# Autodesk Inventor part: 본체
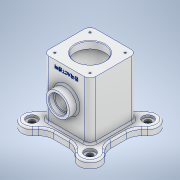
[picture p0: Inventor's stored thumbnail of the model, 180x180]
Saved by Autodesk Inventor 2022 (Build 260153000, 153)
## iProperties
Created: 2022-05
Part Number: 본체
Material: 알루미늄 6061
Document SubType Name: Modeling
Designer: Admin
Density: 2.7 g/cm^3
Appearance: 알루미늄 - 평지
Mass: 1073.02 g
Surface Area: 877.331 cm^2
Volume: 397.416 cm^3
Author: Admin
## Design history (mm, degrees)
sketch "스케치1"
  geometry: L1 (49, 49)-(-49, 49); L2 (-49, 49)-(-49, -49); L3 (-49, -49)-(49, -49); L4 (49, -49)-(49, 49); L5 (49, 49)-(-49, -49); L6 (-49, 49)-(49, -49); L7 (49, -49)-(-49, 49); L8 (61.728, -36.272)-(-36.272, 61.728); L9 (-61.728, 36.272)-(36.272, -61.728); L10 (36.272, 61.728)-(-61.728, -36.272); L11 (-36.272, -61.728)-(61.728, 36.272); L12 (104.238, 0)-(-104.238, 0) reference; L13 (0, -104.238)-(0, 104.238) reference; A1 r 18 centre (49, -49) between (36.272, -61.728) and (61.728, -36.272); A2 r 18 centre (-49, 49) between (-36.272, 61.728) and (-61.728, 36.272); A3 r 18 centre (49, 49) between (61.728, 36.272) and (36.272, 61.728); A4 r 18 centre (-49, -49) between (-61.728, -36.272) and (-36.272, -61.728); 11 further points
  constraints: 24 end point, 8 point on circle, 8 tangent, 4 centre point, 4 midpoint, 3 perpendicular, 1 collinear
  dimensions: "d0" = 98 distance of L3.end L1.start; "d1" = 98 distance of L2.end L3.end; "d2" = 36 distance between parallel lines of L10 L11; "d3" = 36 distance between parallel lines of L9 L8; "d73" = 45 deg angle of L5 L13
extrude "돌출1" new body sketch "스케치1" distance "d4" = 12; taper "d5" = 0 deg
sketch "스케치2" dims "d6" = 140
  geometry: L1 (0, 0)-(-75.016, -75.016); L2 (-104.02, 0)-(99.003, 0) reference; L3 (0, 99.003)-(0, -104.02) reference; 2 further points
  constraints: 2 end point, 1 coincident, 1 point on line, 3 other
  dimensions: "d7" = 45 deg angle of L2 L1
hole "구멍1" sketch "스케치2" at (-49.497, -49.497) diameter "d9" = 10; stored, may be unused: countersink angle "d13" = 90 deg, drill point angle "d15" = 118 deg; dims "d10" = 8, "d11" = 18, "d12" = 4, "d14" = 11.8
sketch "스케치3"
  geometry: L1 (-40, -40)-(40, -40); L2 (40, -40)-(40, 40); L3 (40, 40)-(-40, 40); L4 (-40, 40)-(-40, -40); L5 (-40, -40)-(40, 40); L6 (40, -40)-(-40, 40); 1 further point
  constraints: 12 end point, 2 midpoint, 2 parallel, 1 horizontal, 1 perpendicular
  dimensions: "d16" = 80 distance of L2.end L3.end; "d17" = 80 distance of L3.end L1.start
extrude "돌출2" join sketch "스케치3" distance "d18" = 98; taper "d19" = 0 deg
node "작업 평면1"
sketch "스케치4"
  geometry: L1 (67, 12)-(36.272, 12) reference; C1 r 20 at (0, 61); 2 further points
  constraints: 1 centre point, 1 vertical alignment
  dimensions: "d21" = 40 diameter of C1; "d22" = 49 distance from line of L1 C1.centre
extrude "돌출3" join sketch "스케치4" stored distance "d23" = 98; taper "d24" = 0 deg
sketch "스케치5"
  geometry: L1 (110, 40)-(110, -40) reference; L2 (110, 25)-(98, 25); L3 (98, 25)-(98, 35); L4 (98, 35)-(12, 35); L5 (12, 35)-(12, 25); L6 (12, 25)-(0, 25); L7 (0, 23.544)-(0, -23.544) reference; L8 (-22, 0)-(132, 0) reference; L9 (110, 25)-(110, 0); L10 (110, 0)-(0, 0); L11 (0, 25)-(0, 0)
  constraints: 16 end point, 5 point on line, 4 perpendicular, 1 collinear, 1 midpoint, 1 vertical
  dimensions: "d25" = 12 distance of L2.start L2.end; "d26" = 12 distance of L5.end L6.end; "d27" = 70 diameter of L4 L8; "d28" = 50 diameter of L2 L8
revolve "회전1" sketch "스케치5" stored, may be unused: angle "d29" = 90 deg
sketch "스케치6"
  geometry: C1 r 20 at (0, 0) reference; 2 further points
  constraints: 1 coincident
hole "구멍2" sketch "스케치6" at (0, 0) diameter "d30" = 25; stored, may be unused: countersink angle "d34" = 90 deg, drill point angle "d36" = 118 deg; dims "d31" = 6, "d32" = 30, "d33" = 8, "d35" = 8
fillet "모깎기1" dims "d37" = 25
fillet "모깎기2" dims "d38" = 3
fillet "모깎기3" dims "d39" = 10
fillet "모깎기4" dims "d40" = 3
fillet "모깎기5" dims "d41" = 3
sketch "스케치7"
  geometry: L1 (-30, -30)-(30, -30); L2 (30, -30)-(30, 30); L3 (30, 30)-(-30, 30); L4 (-30, 30)-(-30, -30); L5 (-30, -30)-(30, 30); L6 (30, -30)-(-30, 30); C1 r 25 at (0, 0) reference; 5 further points
  constraints: 12 end point, 4 coincident, 2 midpoint, 2 parallel, 1 horizontal, 1 perpendicular
  dimensions: "d42" = 60 distance of L3.end L1.start; "d43" = 60 distance of L2.end L3.end
hole "구멍3" sketch "스케치7" at (-30, -30), (-30, 30), (30, -30), (30, 30) diameter "d44" = 3.242; stored, may be unused: countersink angle "d48" = 90 deg, drill point angle "d50" = 118 deg; dims "d45" = 8, "d46" = 4, "d47" = 2, "d49" = 10
sketch "스케치8"
  geometry: L1 (30, 30)-(-30, 30); L2 (-30, 30)-(-30, -30); L3 (-30, -30)-(30, -30); L4 (30, -30)-(30, 30); L5 (30, 30)-(-30, -30); L6 (-30, 30)-(30, -30); 5 further points
  constraints: 12 end point, 4 coincident, 2 midpoint, 2 parallel, 1 horizontal, 1 perpendicular
  dimensions: "d53" = 60 distance of L1.start L1.end; "d54" = 60 distance of L3.end L1.start
hole "구멍4" sketch "스케치8" at (30, 30), (30, -30), (-30, -30), (-30, 30) diameter "d55" = 3.242; stored, may be unused: countersink angle "d59" = 90 deg, drill point angle "d61" = 118 deg; dims "d56" = 8, "d57" = 4, "d58" = 2, "d60" = 10
chamfer "모따기1" distance "d62" = 1; stored, may be unused: second distance "d63" = 2, angle "d64" = 45 deg
fillet "모깎기6" dims "d65" = 3
sketch "스케치9"
  geometry: L1 (0, 0)-(60, 0) reference; C1 r 15 at (30, -49) reference; 2 further points
  constraints: 1 vertical alignment, 1 other
  dimensions: "d66" = 10 distance from line of L1 point (30, -10)
feature "엠보싱1" sketch "스케치9" dims "d0" = 98, "d1" = 98, "d2" = 36, "d3" = 36, "d9" = 10, "d11" = 18, "d12" = 4, "d14" = 11.8, "d67" = 0.5, "d68" = 0, "d73" = 45 deg
chamfer "모따기2" distance "d69" = 1; stored, may be unused: second distance "d70" = 2, angle "d71" = 45 deg
node "솔리드1"
mirror "미러1"
mirror "미러2"
feature "A9D066F2-1C7D-4E18-AEED-F7BC21143FA4" dims "d9" = 10, "d10" = 8, "d11" = 18, "d12" = 4, "d13" = 90 deg, "d14" = 11.8, "d15" = 118 deg
other parameters: "d20" = 55
